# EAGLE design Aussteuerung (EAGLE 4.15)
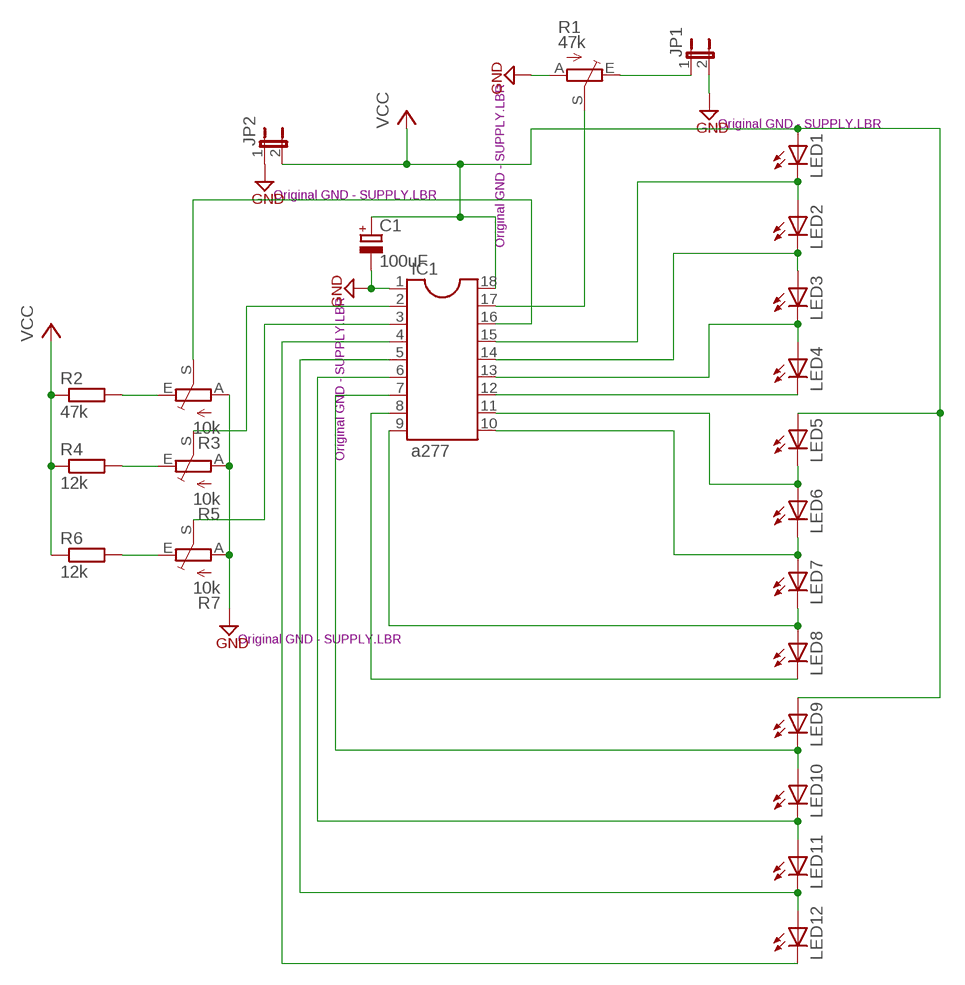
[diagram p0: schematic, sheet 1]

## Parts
C1  100uF  CPOL-EUE2.5-6  [E2,5-6]
IC1  a277  DIL18  [DIL18]
JP1  JP1E  [JP1]
JP2  JP1E  [JP1]
LED1  LEDSQR5.7X3.2  [U57X32]
LED2  LEDSQR5.7X3.2  [U57X32]
LED3  LEDSQR5.7X3.2  [U57X32]
LED4  LEDSQR5.7X3.2  [U57X32]
LED5  LEDSQR5.7X3.2  [U57X32]
LED6  LEDSQR5.7X3.2  [U57X32]
LED7  LEDSQR5.7X3.2  [U57X32]
LED8  LEDSQR5.7X3.2  [U57X32]
LED9  LEDSQR5.7X3.2  [U57X32]
LED10  LEDSQR5.7X3.2  [U57X32]
LED11  LEDSQR5.7X3.2  [U57X32]
LED12  LEDSQR5.7X3.2  [U57X32]
R1  47k  TRIM_EU-CA9V  [CA9V]
R2  47k  R-EU_0207/10  [0207/10]
R3  10k  TRIM_EU-CA9V  [CA9V]
R4  12k  R-EU_0207/10  [0207/10]
R5  10k  TRIM_EU-CA9V  [CA9V]
R6  12k  R-EU_0207/10  [0207/10]
R7  10k  TRIM_EU-CA9V  [CA9V]

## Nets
GND: C1.- IC1.1 JP1.2 JP2.1 R1.A R3.A R5.A R7.A
N$1: IC1.15 LED1.K(C) LED2.A
N$2: IC1.14 LED2.K(C) LED3.A
N$3: IC1.13 LED3.K(C) LED4.A
N$4: IC1.12 LED4.K(C)
N$5: IC1.17 R1.S
N$6: R2.2 R3.E
N$7: IC1.8 LED8.K(C)
N$8: IC1.7 LED9.K(C) LED10.A
N$9: IC1.11 LED5.K(C) LED6.A
N$10: IC1.6 LED10.K(C) LED11.A
N$11: IC1.9 LED7.K(C) LED8.A
N$12: IC1.5 LED11.K(C) LED12.A
N$13: IC1.4 LED12.K(C)
N$15: JP1.1 R1.E
N$16: IC1.10 LED6.K(C) LED7.A
N$17: IC1.16 R3.S
N$18: R4.2 R5.E
N$19: R6.2 R7.E
N$20: IC1.2 R5.S
N$21: IC1.3 R7.S
VCC: C1.+ IC1.18 JP2.2 LED1.A LED5.A LED9.A R2.1 R4.1 R6.1

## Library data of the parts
C1 = rcl:CPOL-EU: POLARIZED CAPACITOR, European symbol
IC1 = ic-package:DIL18: Dual In Line
JP1 JP2 = jumper:JP1E: JUMPER
LED1-LED12 = led:LED: LED
R1 R3 R5 R7 = pot:TRIM_EU-: POTENTIOMETER
R2 R4 R6 = rcl:R-EU_: RESISTOR, European symbol

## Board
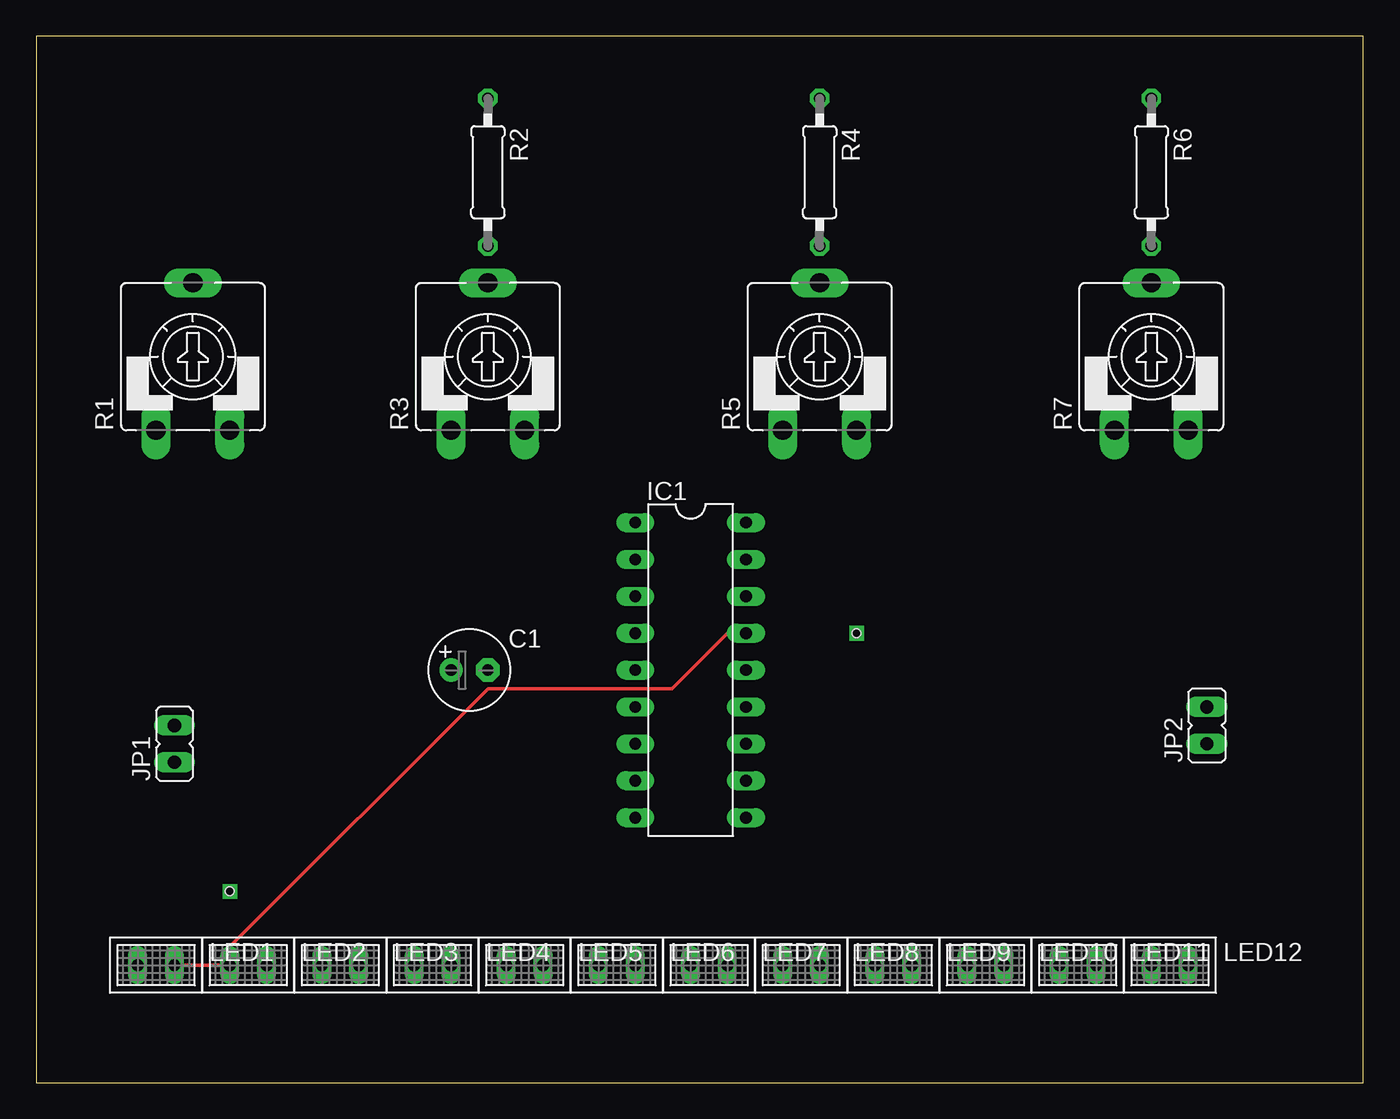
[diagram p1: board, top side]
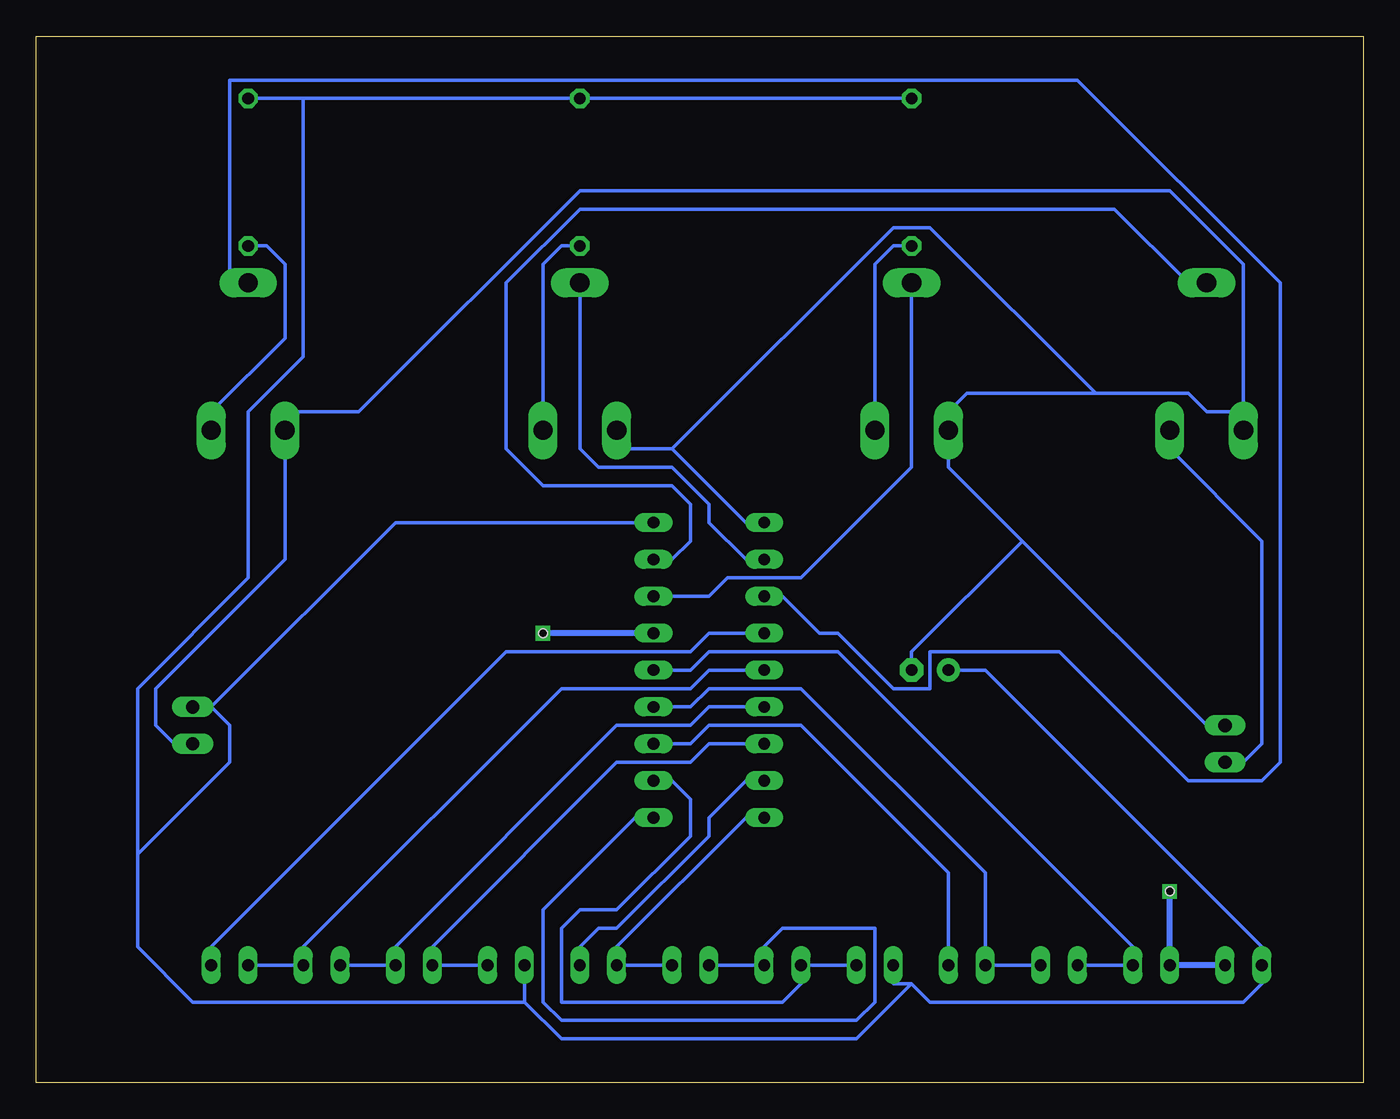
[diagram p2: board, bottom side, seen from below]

Size 91.42 x 72.06 mm. Coordinates in mm from the lower left corner, seen from the top.
Outline: 0,0 91.42,0 91.42,72.06 0,72.06 0,0
Copper layers (1*16): Top 0.035mm / dielectric 1.5mm / Bottom 0.035mm
Design rules "default": minimum track width 10mil, minimum drill 24mil, track to track 8mil, track to pad 8mil, pad to pad 8mil, via to via 8mil, smd to smd 8mil, copper to edge 40mil, drill to drill 8mil, minimum pad ring 10mil, minimum via ring 8mil, stop-mask expansion 4mil, vias tented up to drill 0mil, thermal gap 10mil
Holes 0.6 mm at 13.33,13.17 56.51,30.95

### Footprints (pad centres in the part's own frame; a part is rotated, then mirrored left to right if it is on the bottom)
E2,5-6 = drill 0.813 pad 1.6 round: + -1.27,0 | drill 0.813 pad 1.6 octagon: - 1.27,0
DIL18 = drill 0.813 long: 1 -10.16,-3.81; 2 -7.62,-3.81; 3 -5.08,-3.81; 4 -2.54,-3.81; 5 0,-3.81; 6 2.54,-3.81; 7 5.08,-3.81; 8 7.62,-3.81; 9 10.16,-3.81; 10 10.16,3.81; 11 7.62,3.81; 12 5.08,3.81; 13 2.54,3.81; 14 0,3.81; 15 -2.54,3.81; 16 -5.08,3.81; 17 -7.62,3.81; 18 -10.16,3.81
JP1 = drill 0.914 long: 1 0,-1.27; 2 0,1.27
U57X32 = drill 0.813 long: A -1.27,0; K 1.27,0
CA9V = drill 1.321 long: A -2.54,-5.08; E 2.54,-5.08; S 0,5.08
0207/10 = drill 0.813 octagon: 1 -5.08,0; 2 5.08,0

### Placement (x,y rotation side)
C1  29.84,28.41 0 top
IC1  45.08,28.41 270 top
JP1  9.52,23.33 0 top
JP2  80.64,24.6 0 top
LED1  8.25,8.09 0 top
LED2  14.6,8.09 0 top
LED3  20.95,8.09 0 top
LED4  27.3,8.09 0 top
LED5  33.65,8.09 0 top
LED6  40,8.09 0 top
LED7  46.35,8.09 0 top
LED8  52.7,8.09 0 top
LED9  59.05,8.09 0 top
LED10  65.4,8.09 0 top
LED11  71.75,8.09 0 top
LED12  78.1,8.09 0 top
R1  10.79,50 0 top
R2  31.11,62.7 270 top
R3  31.11,50 0 top
R4  53.97,62.7 270 top
R5  53.97,50 0 top
R6  76.83,62.7 270 top
R7  76.83,50 0 top

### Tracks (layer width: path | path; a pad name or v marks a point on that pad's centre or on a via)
GND
  Bottom 0.254: JP2.1 81.91,23.33 83.18,24.6 83.18,27.14 74.29,36.03 R7.A 74.29,46.19 69.21,46.19 53.97,61.43 13.33,61.43 8.25,56.35 8.25,46.19 | 47.62,43.65 42.54,38.57 IC1.1 | 47.62,43.65 51.43,43.65 R5.A | 23.49,37.3 28.57,42.38 R3.A 28.57,46.19 27.3,47.46 18.41,47.46 | 23.49,37.3 10.79,24.6 JP1.2 | C1.- 31.11,29.68 23.49,37.3 | 8.25,46.19 10.79,46.19 12.06,47.46 18.41,47.46 | 8.25,46.19 R1.A | 47.62,43.65 32.38,58.89 29.84,58.89 18.41,47.46
N$1  (via drill 0.6)
  Top 0.254: LED1.K LED2.A 13.33,9.36 31.11,27.14 43.81,27.14 47.62,30.95 IC1.15
  Bottom 0.254: LED1.K LED2.A
  Bottom 0.406: v13.33,13.17 LED2.A LED1.K | IC1.15 v56.51,30.95
N$2
  Bottom 0.254: IC1.14 46.35,28.41 45.08,29.68 36.19,29.68 15.87,9.36 LED2.K LED3.A
N$3
  Bottom 0.254: IC1.13 46.35,25.87 45.08,27.14 38.73,27.14 26.03,14.44 LED4.A LED3.K
N$4
  Bottom 0.254: LED4.K 28.57,14.44 38.73,24.6 45.08,24.6 46.35,23.33 IC1.12
N$5
  Bottom 0.254: IC1.17 47.62,36.03 46.35,37.3 46.35,39.84 47.62,41.11 56.51,41.11 59.05,43.65 59.05,55.08 53.97,60.16 17.14,60.16 12.06,55.08 R1.S
N$6
  Bottom 0.254: R2.2 32.38,57.62 33.65,56.35 R3.E
N$7
  Bottom 0.254: IC1.8 42.54,20.79 45.08,18.25 45.08,16.98 51.43,10.63 52.7,10.63 53.97,9.36 LED8.K
N$8
  Bottom 0.254: LED9.K LED10.A 64.13,9.36 51.43,22.06 46.35,22.06 45.08,23.33 IC1.7
N$9
  Bottom 0.254: LED5.K LED6.A 38.73,6.82 40,5.55 55.24,5.55 55.24,10.63 53.97,11.9 51.43,11.9 46.35,16.98 46.35,19.52 47.62,20.79 IC1.11
N$10
  Bottom 0.254: LED11.A LED10.K 66.67,9.36 51.43,24.6 46.35,24.6 45.08,25.87 IC1.6
N$11
  Bottom 0.254: LED7.K LED8.A 51.43,9.36 42.54,18.25 IC1.9
N$12
  Bottom 0.254: LED12.A LED11.K 73.02,9.36 55.24,27.14 46.35,27.14 45.08,28.41 IC1.5
N$13
  Bottom 0.254: IC1.4 45.08,30.95 46.35,29.68 59.05,29.68 79.37,9.36 LED12.K
N$15
  Bottom 0.254: JP1.1 8.25,22.06 6.98,23.33 6.98,37.3 13.33,43.65 R1.E
N$16
  Bottom 0.254: LED7.A LED6.K 41.27,9.36 40,10.63 33.65,10.63 33.65,5.55 34.92,4.28 55.24,4.28 56.51,5.55 56.51,11.9 50.16,18.25 IC1.10
N$17
  Bottom 0.254: R3.S 31.11,42.38 38.73,34.76 43.81,34.76 45.08,33.49 IC1.16
N$18
  Bottom 0.254: R4.2 55.24,57.62 56.51,56.35 R5.E
N$19
  Bottom 0.254: R6.2 75.56,57.62 74.29,56.35 74.29,51.27 79.37,46.19 R7.E
N$20
  Bottom 0.254: R5.S 53.97,43.65 52.7,42.38 47.62,42.38 45.08,39.84 45.08,38.57 42.54,36.03 IC1.2
N$21
  Bottom 0.254: IC1.3 40,33.49 37.46,30.95 36.19,30.95 32.38,27.14 29.84,27.14 29.84,29.68 20.95,29.68 12.06,20.79 6.98,20.79 5.71,22.06 5.71,55.08 19.68,69.05 78.1,69.05 78.1,55.08 R7.S
VCC
  Bottom 0.254: 79.37,25.87 66.67,38.57 IC1.18 | 73.02,67.78 R4.1 R2.1 | 73.02,67.78 R6.1 | C1.+ 26.03,28.41 6.98,9.36 LED1.A 6.98,6.82 8.25,5.55 29.84,5.55 31.11,6.82 | 31.11,6.82 32.38,6.82 LED5.A | 57.78,5.55 55.24,3.01 34.92,3.01 31.11,6.82 | 57.78,5.55 LED9.A | 73.02,67.78 73.02,50 76.83,46.19 76.83,34.76 84.45,27.14 84.45,15.71 | 84.45,15.71 84.45,9.36 80.64,5.55 57.78,5.55 | 79.37,25.87 78.1,24.6 78.1,22.06 84.45,15.71 | 79.37,25.87 JP2.2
